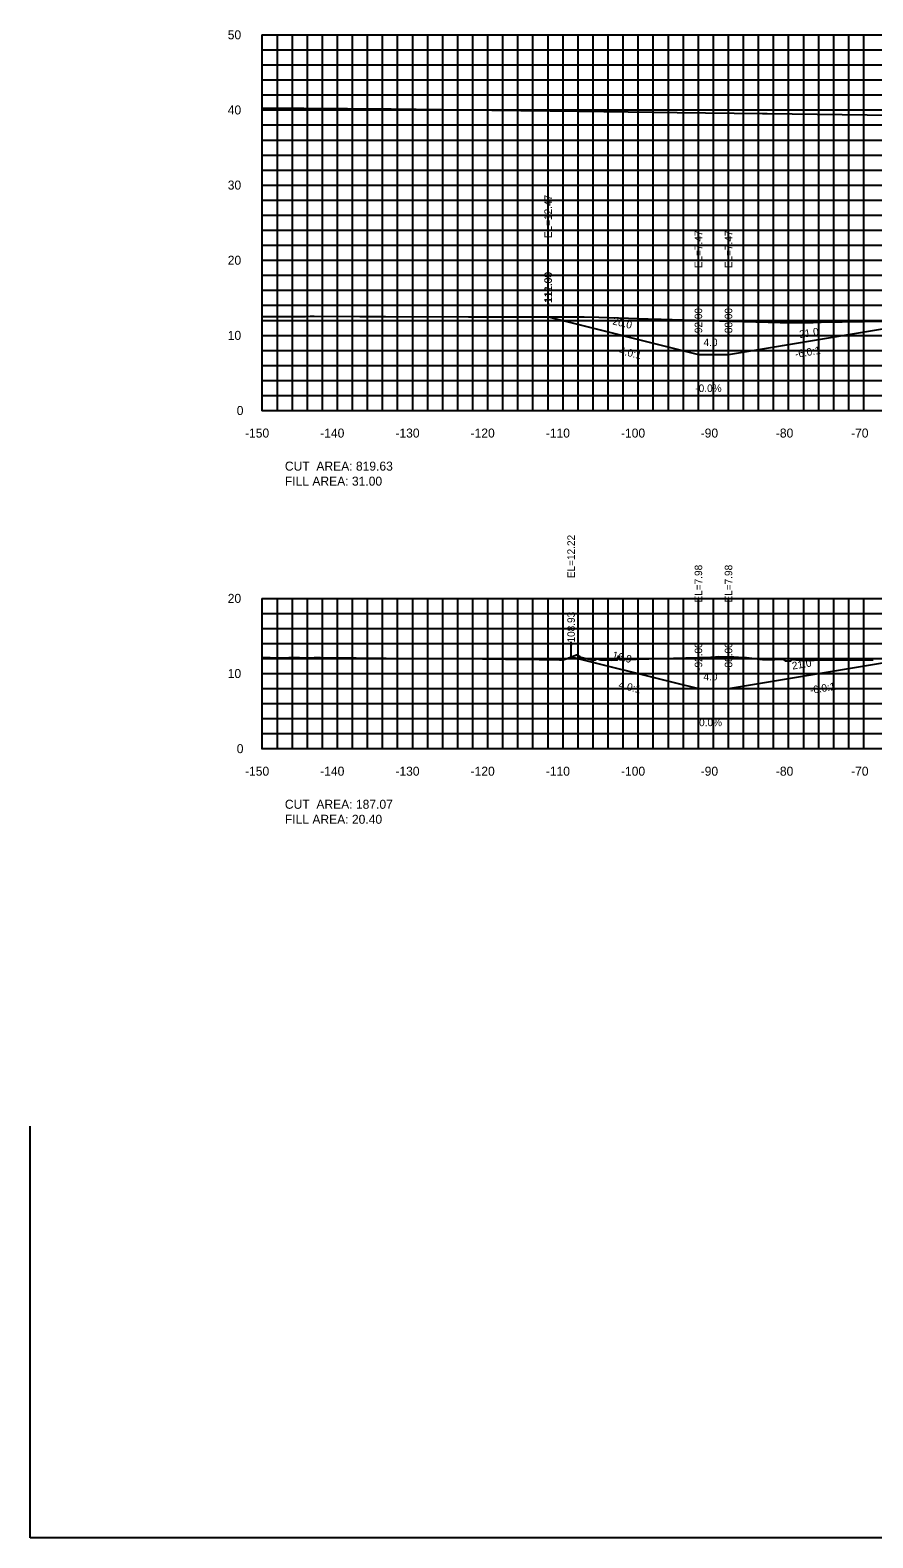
# Model space of a CAD drawing. Extents: x 1797419 to 1809236, y 248759 to 251512.
# Drawn here: x 1802790.1 to 1802902.2, y 249994.4 to 250195 of the extents above; entities that cross this region are included whole.
import ezdxf

# ---------------------------------------------------------------- set-up
doc = ezdxf.new("R2010")
doc.units = 0
for name, color, linetype in [('10', 7, 'Continuous'), ('3', 7, 'Continuous'), ('31', 7, 'Continuous'), ('4', 7, 'Continuous'), ('60', 7, 'Continuous'), ('ANNO-TXT', 7, 'Continuous'), ('CL-CNST', 7, 'Continuous'), ('Level 55', 7, 'Continuous'), ('Level 62', 7, 'Continuous'), ('M-ROADS', 7, 'Continuous')]:
    doc.layers.add(name, color=color, linetype=linetype)

msp = doc.modelspace()

# ---------------------------------------------------------------- linework, layer by layer
for p, q in [((1802859.01, 250156.9), (1802859.01, 250158.9)), ((1802859.01, 250156.9), (1802859.01, 250158.9)), ((1802879, 250151.9), (1802879, 250153.9)), ((1802879, 250151.9), (1802879, 250153.9)), ((1802883, 250151.9), (1802883, 250153.9)), ((1802862.07, 250111.65), (1802862.07, 250113.65)), ((1802862.07, 250111.65), (1802862.07, 250113.65)), ((1802879, 250107.42), (1802879, 250109.42)), ((1802883, 250107.42), (1802883, 250109.42))]:
    msp.add_line(p, q)
at = {"layer": '60'}
for p, q in [((1802820.94, 250194.43), (1802821, 250194.43)), ((1802821, 250144.43), (1802821, 250194.43)), ((1802820.94, 250184.43), (1802821, 250184.43)), ((1802820.94, 250174.43), (1802821, 250174.43)), ((1802820.94, 250164.43), (1802821, 250164.43)), ((1802820.94, 250154.43), (1802821, 250154.43)), ((1802820.94, 250144.43), (1802821, 250144.43)), ((1802821, 250144.43), (1803121, 250144.43)), ((1802821, 250144.37), (1802821, 250144.43)), ((1802831, 250144.37), (1802831, 250144.43)), ((1802841, 250144.37), (1802841, 250144.43)), ((1802851, 250144.37), (1802851, 250144.43)), ((1802861, 250144.37), (1802861, 250144.43)), ((1802871, 250144.37), (1802871, 250144.43)), ((1802881, 250144.37), (1802881, 250144.43)), ((1802891, 250144.37), (1802891, 250144.43)), ((1802901, 250144.37), (1802901, 250144.43)), ((1802820.94, 250119.43), (1802821, 250119.43)), ((1802821, 250099.43), (1802821, 250119.43)), ((1802820.94, 250109.43), (1802821, 250109.43)), ((1802820.94, 250099.43), (1802821, 250099.43)), ((1802821, 250099.43), (1803121, 250099.43)), ((1802821, 250099.37), (1802821, 250099.43)), ((1802831, 250099.37), (1802831, 250099.43)), ((1802841, 250099.37), (1802841, 250099.43)), ((1802851, 250099.37), (1802851, 250099.43)), ((1802861, 250099.37), (1802861, 250099.43)), ((1802871, 250099.37), (1802871, 250099.43)), ((1802881, 250099.37), (1802881, 250099.43)), ((1802891, 250099.37), (1802891, 250099.43)), ((1802901, 250099.37), (1802901, 250099.43))]:
    msp.add_line(p, q, dxfattribs=at)
at = {"layer": 'CL-CNST'}
for points in [[(1802821, 250184.73), (1802826.54, 250184.67), (1802838.13, 250184.56), (1802851.51, 250184.4), (1802863.13, 250184.27), (1802876.16, 250184.11), (1802887.53, 250183.97), (1802887.85, 250183.97), (1802888.13, 250183.96), (1802901.45, 250183.78), (1802913.13, 250183.62), (1802926.41, 250183.43), (1802938.13, 250183.26), (1802951.38, 250183.05), (1802963.13, 250182.86), (1802976.35, 250182.64), (1802988.13, 250182.44), (1803001.31, 250182.21), (1803013.13, 250181.99), (1803021.41, 250181.84), (1803028.86, 250181.7), (1803033.73, 250181.6)], [(1802859.01, 250156.9), (1802859.01, 250156.9), (1802879, 250151.9), (1802883, 250151.9), (1802883.01, 250151.9), (1802890.2, 250153.1), (1802904, 250155.4), (1802906, 250155.48), (1802908.8, 250155.59), (1802910, 250155.64), (1802910.02, 250155.64), (1802943.79, 250156.39), (1802971, 250156.98), (1803023.67, 250158.08), (1803025.91, 250157.99), (1803027.67, 250157.92), (1803029.67, 250157.84), (1803029.68, 250157.84), (1803038.78, 250156.32)], [(1802862.07, 250111.65), (1802862.07, 250111.65), (1802875.77, 250108.22), (1802879, 250107.42), (1802883, 250107.42), (1802904, 250110.92), (1802906, 250111), (1802910, 250111.16), (1802955.02, 250112.15), (1802971, 250112.5), (1802971, 250112.5), (1802990.3, 250112.57), (1803042.76, 250112.75), (1803044.92, 250112.66), (1803046.76, 250112.59), (1803048.76, 250112.51), (1803055.3, 250111.42), (1803069.76, 250109.01), (1803069.76, 250109.01), (1803071.67, 250109.01), (1803073.76, 250109.67), (1803075.3, 250109.92), (1803081.48, 250110.94)]]:
    msp.add_lwpolyline(points, dxfattribs=at)
at = {"layer": 'Level 55'}
for p, q in [((1802790.13, 249994.4), (1802790.13, 250049.17)), ((1803817.39, 249994.4), (1802790.13, 249994.4))]:
    msp.add_line(p, q, dxfattribs=at)
at = {"layer": 'Level 62'}
for p, q in [((1802821, 250194.43), (1803121, 250194.43)), ((1802821, 250144.43), (1802821, 250194.43)), ((1802823, 250144.43), (1802823, 250194.43)), ((1802825, 250144.43), (1802825, 250194.43)), ((1802827, 250144.43), (1802827, 250194.43)), ((1802829, 250144.43), (1802829, 250194.43)), ((1802831, 250144.43), (1802831, 250194.43)), ((1802833, 250144.43), (1802833, 250194.43)), ((1802835, 250144.43), (1802835, 250194.43)), ((1802837, 250144.43), (1802837, 250194.43)), ((1802839, 250144.43), (1802839, 250194.43)), ((1802841, 250144.43), (1802841, 250194.43)), ((1802843, 250144.43), (1802843, 250194.43)), ((1802845, 250144.43), (1802845, 250194.43)), ((1802847, 250144.43), (1802847, 250194.43)), ((1802849, 250144.43), (1802849, 250194.43)), ((1802851, 250144.43), (1802851, 250194.43)), ((1802853, 250144.43), (1802853, 250194.43)), ((1802855, 250144.43), (1802855, 250194.43)), ((1802857, 250144.43), (1802857, 250194.43)), ((1802859, 250144.43), (1802859, 250194.43)), ((1802861, 250144.43), (1802861, 250194.43)), ((1802863, 250144.43), (1802863, 250194.43)), ((1802865, 250144.43), (1802865, 250194.43)), ((1802867, 250144.43), (1802867, 250194.43)), ((1802869, 250144.43), (1802869, 250194.43)), ((1802871, 250144.43), (1802871, 250194.43)), ((1802873, 250144.43), (1802873, 250194.43)), ((1802875, 250144.43), (1802875, 250194.43)), ((1802877, 250144.43), (1802877, 250194.43)), ((1802879, 250144.43), (1802879, 250194.43)), ((1802881, 250144.43), (1802881, 250194.43)), ((1802883, 250144.43), (1802883, 250194.43)), ((1802885, 250144.43), (1802885, 250194.43)), ((1802887, 250144.43), (1802887, 250194.43)), ((1802889, 250144.43), (1802889, 250194.43)), ((1802891, 250144.43), (1802891, 250194.43)), ((1802893, 250144.43), (1802893, 250194.43)), ((1802895, 250144.43), (1802895, 250194.43)), ((1802897, 250144.43), (1802897, 250194.43)), ((1802899, 250144.43), (1802899, 250194.43)), ((1802901, 250144.43), (1802901, 250194.43)), ((1802821, 250192.43), (1803121, 250192.43)), ((1802821, 250190.43), (1803121, 250190.43)), ((1802821, 250188.43), (1803121, 250188.43)), ((1802821, 250186.43), (1803121, 250186.43)), ((1802821, 250184.43), (1803121, 250184.43)), ((1802821, 250182.43), (1803121, 250182.43)), ((1802821, 250180.43), (1803121, 250180.43)), ((1802821, 250178.43), (1803121, 250178.43)), ((1802821, 250176.43), (1803121, 250176.43)), ((1802821, 250174.43), (1803121, 250174.43)), ((1802821, 250172.43), (1803121, 250172.43)), ((1802821, 250170.43), (1803121, 250170.43)), ((1802821, 250168.43), (1803121, 250168.43)), ((1802821, 250166.43), (1803121, 250166.43)), ((1802821, 250164.43), (1803121, 250164.43)), ((1802821, 250162.43), (1803121, 250162.43)), ((1802821, 250160.43), (1803121, 250160.43)), ((1802821, 250158.43), (1803121, 250158.43)), ((1802821, 250156.43), (1803121, 250156.43)), ((1802821, 250154.43), (1803121, 250154.43)), ((1802821, 250152.43), (1803121, 250152.43)), ((1802821, 250150.43), (1803121, 250150.43)), ((1802821, 250148.43), (1803121, 250148.43)), ((1802821, 250146.43), (1803121, 250146.43)), ((1802821, 250144.43), (1803121, 250144.43)), ((1802821, 250119.43), (1803121, 250119.43)), ((1802821, 250099.43), (1802821, 250119.43)), ((1802823, 250099.43), (1802823, 250119.43)), ((1802825, 250099.43), (1802825, 250119.43)), ((1802827, 250099.43), (1802827, 250119.43)), ((1802829, 250099.43), (1802829, 250119.43)), ((1802831, 250099.43), (1802831, 250119.43)), ((1802833, 250099.43), (1802833, 250119.43)), ((1802835, 250099.43), (1802835, 250119.43)), ((1802837, 250099.43), (1802837, 250119.43)), ((1802839, 250099.43), (1802839, 250119.43)), ((1802841, 250099.43), (1802841, 250119.43)), ((1802843, 250099.43), (1802843, 250119.43)), ((1802845, 250099.43), (1802845, 250119.43)), ((1802847, 250099.43), (1802847, 250119.43)), ((1802849, 250099.43), (1802849, 250119.43)), ((1802851, 250099.43), (1802851, 250119.43)), ((1802853, 250099.43), (1802853, 250119.43)), ((1802855, 250099.43), (1802855, 250119.43)), ((1802857, 250099.43), (1802857, 250119.43)), ((1802859, 250099.43), (1802859, 250119.43)), ((1802861, 250099.43), (1802861, 250119.43)), ((1802863, 250099.43), (1802863, 250119.43)), ((1802865, 250099.43), (1802865, 250119.43)), ((1802867, 250099.43), (1802867, 250119.43)), ((1802869, 250099.43), (1802869, 250119.43)), ((1802871, 250099.43), (1802871, 250119.43)), ((1802873, 250099.43), (1802873, 250119.43)), ((1802875, 250099.43), (1802875, 250119.43)), ((1802877, 250099.43), (1802877, 250119.43)), ((1802879, 250099.43), (1802879, 250119.43)), ((1802881, 250099.43), (1802881, 250119.43)), ((1802883, 250099.43), (1802883, 250119.43)), ((1802885, 250099.43), (1802885, 250119.43)), ((1802887, 250099.43), (1802887, 250119.43)), ((1802889, 250099.43), (1802889, 250119.43)), ((1802891, 250099.43), (1802891, 250119.43)), ((1802893, 250099.43), (1802893, 250119.43)), ((1802895, 250099.43), (1802895, 250119.43)), ((1802897, 250099.43), (1802897, 250119.43)), ((1802899, 250099.43), (1802899, 250119.43)), ((1802901, 250099.43), (1802901, 250119.43)), ((1802821, 250117.43), (1803121, 250117.43)), ((1802821, 250115.43), (1803121, 250115.43)), ((1802821, 250113.43), (1803121, 250113.43)), ((1802821, 250111.43), (1803121, 250111.43)), ((1802821, 250109.43), (1803121, 250109.43)), ((1802821, 250107.43), (1803121, 250107.43)), ((1802821, 250105.43), (1803121, 250105.43)), ((1802821, 250103.43), (1803121, 250103.43)), ((1802821, 250101.43), (1803121, 250101.43)), ((1802821, 250099.43), (1803121, 250099.43))]:
    msp.add_line(p, q, dxfattribs=at)
at = {"layer": 'M-ROADS'}
for points in [[(1802821, 250156.96), (1802826.21, 250156.96), (1802826.76, 250156.96), (1802827.36, 250156.97), (1802827.88, 250156.97), (1802827.9, 250156.97), (1802833.97, 250156.95), (1802837.37, 250156.94), (1802848.43, 250156.91), (1802848.47, 250156.91), (1802850.75, 250156.9), (1802851.73, 250156.9), (1802851.93, 250156.9), (1802852.64, 250156.9), (1802854.11, 250156.9), (1802858.67, 250156.9), (1802863.55, 250156.89), (1802863.79, 250156.89), (1802865.74, 250156.85), (1802872.31, 250156.62), (1802874.03, 250156.6), (1802876.96, 250156.52), (1802889.85, 250156.16), (1802890.14, 250156.15), (1802892.27, 250156.15), (1802892.71, 250156.15), (1802894.26, 250156.15), (1802895.31, 250156.19), (1802903.71, 250156.32)], [(1802821, 250111.57), (1802822.03, 250111.56), (1802822.57, 250111.51), (1802822.63, 250111.51), (1802823.98, 250111.5), (1802824.52, 250111.56), (1802824.58, 250111.56), (1802824.66, 250111.56), (1802825.93, 250111.57), (1802826.31, 250111.53), (1802826.66, 250111.5), (1802827.14, 250111.52), (1802827.88, 250111.55), (1802828.11, 250111.56), (1802828.74, 250111.55), (1802829.61, 250111.52), (1802829.83, 250111.51), (1802829.9, 250111.52), (1802830.82, 250111.52), (1802831.7, 250111.5), (1802832.12, 250111.5), (1802832.92, 250111.51), (1802833.49, 250111.5), (1802834.52, 250111.49), (1802834.94, 250111.49), (1802835.26, 250111.49), (1802836.87, 250111.48), (1802836.95, 250111.48), (1802837.02, 250111.48), (1802837.47, 250111.49), (1802844.97, 250111.44), (1802850.28, 250111.38), (1802853.36, 250111.35), (1802855.25, 250111.32), (1802856.72, 250111.32), (1802857.8, 250111.3), (1802858.64, 250111.29), (1802859.3, 250111.29), (1802859.84, 250111.28), (1802860.27, 250111.29), (1802860.52, 250111.27), (1802860.68, 250111.26), (1802860.81, 250111.26), (1802860.84, 250111.3), (1802860.87, 250111.26), (1802861.07, 250111.26), (1802861.26, 250111.36), (1802862.8, 250111.91), (1802862.96, 250111.84), (1802863.12, 250111.77), (1802863.19, 250111.65), (1802863.36, 250111.6), (1802864.76, 250111.25), (1802865.2, 250111.27), (1802865.31, 250111.27), (1802865.41, 250111.37), (1802865.55, 250111.37), (1802866.04, 250111.25), (1802867.4, 250111.22), (1802868.22, 250111.25), (1802868.33, 250111.73), (1802868.63, 250111.27), (1802868.69, 250111.28), (1802868.72, 250111.28), (1802868.95, 250111.28), (1802869.06, 250111.28), (1802880.63, 250111.6), (1802880.8, 250111.61), (1802881.7, 250111.68), (1802882.23, 250111.66), (1802882.25, 250111.66), (1802882.27, 250111.66), (1802882.32, 250111.66), (1802882.35, 250111.66), (1802882.37, 250111.66), (1802882.4, 250111.66), (1802882.44, 250111.66), (1802882.52, 250111.66), (1802882.56, 250111.66), (1802882.6, 250111.66), (1802882.66, 250111.65), (1802882.71, 250111.65), (1802882.79, 250111.65), (1802882.86, 250111.65), (1802882.95, 250111.65), (1802883.08, 250111.65), (1802883.21, 250111.65), (1802883.36, 250111.65), (1802883.49, 250111.65), (1802883.62, 250111.65), (1802883.73, 250111.65), (1802884.95, 250111.58), (1802885.05, 250111.59), (1802887.53, 250111.3), (1802887.55, 250111.3), (1802887.76, 250111.28), (1802888.94, 250111.26), (1802889.43, 250111.35), (1802889.99, 250111.33), (1802890.22, 250111.32), (1802890.53, 250111.1), (1802891.27, 250111.1), (1802891.52, 250111.28), (1802892.86, 250111.17), (1802892.89, 250111.15), (1802892.97, 250111.15), (1802892.98, 250111.16), (1802893.04, 250111.15), (1802894.4, 250111.19), (1802895.31, 250111.25), (1802895.89, 250111.27), (1802896.3, 250111.26), (1802897.2, 250111.24), (1802898.49, 250111.26), (1802898.54, 250111.26), (1802898.62, 250111.26), (1802899.82, 250111.24), (1802900.69, 250111.25), (1802901.13, 250111.25), (1802901.83, 250111.25), (1802902.22, 250111.24)]]:
    msp.add_lwpolyline(points, dxfattribs=at)

# ---------------------------------------------------------------- texts
for s, rotation, p in [('4.0:1', 345.9637, (1802868.4, 250151.97)), ('-6.0:1', 9.4624, (1802891.93, 250151.43)), ('4.0:1', 345.9635, (1802868.31, 250107.51)), ('-6.0:1', 9.4623, (1802893.91, 250106.7))]:
    msp.add_text(s, height=1, rotation=rotation).set_placement(p)
at = {"layer": '10'}
for s, p in [('-150', (1802818.7, 250140.83)), ('-140', (1802828.7, 250140.83)), ('-130', (1802838.7, 250140.83)), ('-120', (1802848.7, 250140.83)), ('-110', (1802858.7, 250140.83)), ('-100', (1802868.7, 250140.83)), ('-90', (1802879.3, 250140.83)), ('-80', (1802889.3, 250140.83)), ('-70', (1802899.3, 250140.83)), ('-150', (1802818.7, 250095.83)), ('-140', (1802828.7, 250095.83)), ('-130', (1802838.7, 250095.83)), ('-120', (1802848.7, 250095.83)), ('-110', (1802858.7, 250095.83)), ('-100', (1802868.7, 250095.83)), ('-90', (1802879.3, 250095.83)), ('-80', (1802889.3, 250095.83)), ('-70', (1802899.3, 250095.83))]:
    msp.add_text(s, height=1.2, dxfattribs=at).set_placement(p)
at = {"layer": '3'}
for s, p in [('EL=12.47', (1802859.51, 250167.37)), ('EL=12.47', (1802859.51, 250167.37)), ('EL=7.47', (1802879.5, 250163.37)), ('EL=7.47', (1802879.5, 250163.37)), ('EL=7.47', (1802883.5, 250163.37)), ('-111.99', (1802859.51, 250158.36)), ('-112.00', (1802859.51, 250158.29)), ('-92.00', (1802879.5, 250154.28)), ('-92.00', (1802879.5, 250154.28)), ('-88.00', (1802883.5, 250154.28)), ('EL=12.22', (1802862.57, 250122.12)), ('EL=12.22', (1802862.57, 250122.12)), ('EL=7.98', (1802879.5, 250118.88)), ('EL=7.98', (1802883.5, 250118.88)), ('-108.93', (1802862.57, 250113.11)), ('-108.93', (1802862.57, 250113.11)), ('-92.00', (1802879.5, 250109.79)), ('-88.00', (1802883.5, 250109.79))]:
    msp.add_text(s, height=1, rotation=90, dxfattribs=at).set_placement(p)
at = {"layer": '31'}
for s, p in [('50', (1802816.4, 250193.83)), ('40', (1802816.4, 250183.83)), ('30', (1802816.4, 250173.83)), ('20', (1802816.4, 250163.83)), ('10', (1802816.4, 250153.83)), ('0', (1802817.6, 250143.83)), ('20', (1802816.4, 250118.83)), ('10', (1802816.4, 250108.83)), ('0', (1802817.6, 250098.83))]:
    msp.add_text(s, height=1.2, dxfattribs=at).set_placement(p)
at = {"layer": '4'}
for s, rotation, p in [('20.0', 345.9637, (1802867.51, 250155.91)), ('21.0', 9.4624, (1802892.5, 250154.06)), ('4.0', 0, (1802879.68, 250153)), ('-0.0%', 0, (1802878.59, 250146.9)), ('16.9', 345.9635, (1802867.46, 250111.44)), ('21.0', 9.4623, (1802891.53, 250109.95))]:
    msp.add_text(s, height=1, rotation=rotation, dxfattribs=at).set_placement(p)
for s, p in [('4.0', (1802879.68, 250108.52)), ('0.0%', (1802879.09, 250102.42))]:
    msp.add_text(s, height=1, dxfattribs=at).set_placement(p)
at = {"layer": '60'}
for p in [(1802821, 250144.43), (1802821, 250099.43)]:
    msp.add_text('-', height=0.0001, dxfattribs=at).set_placement(p)
at = {"layer": 'ANNO-TXT'}
for s, p in [('CUT  AREA: 819.63', (1802824, 250136.43)), ('FILL AREA: 31.00', (1802824, 250134.43)), ('CUT  AREA: 187.07', (1802824, 250091.43)), ('FILL AREA: 20.40', (1802824, 250089.43))]:
    msp.add_text(s, height=1.2, dxfattribs=at).set_placement(p)

doc.saveas('drawing.dxf')
